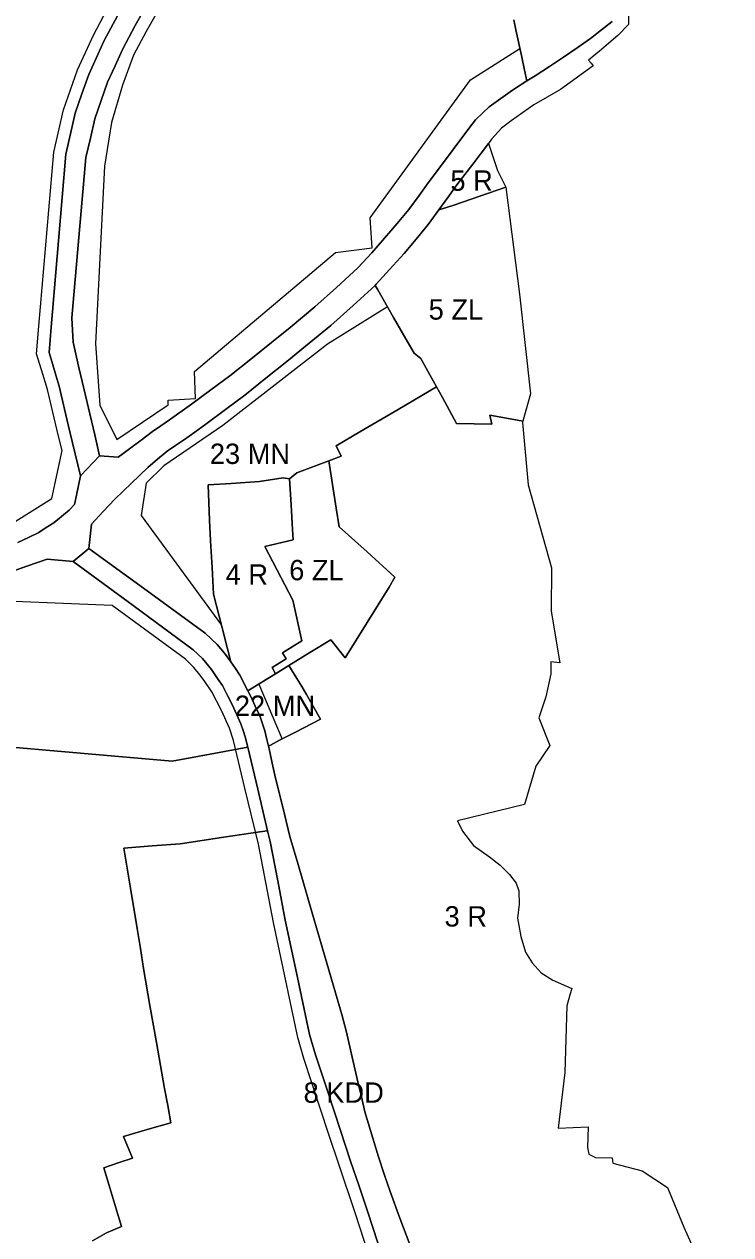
# Model space of a CAD drawing. Extents: x 7423432 to 7425824, y 5537848 to 5539677.
# Drawn here: x 7425463 to 7425809, y 5538619 to 5539213 of the extents above; entities that cross this region are included whole.
import ezdxf

# ---------------------------------------------------------------- set-up
doc = ezdxf.new("R2010")
doc.units = 0
for name, color, linetype in [('linie_rozgraniczajace', 7, 'Continuous'), ('linie_zabudowy_nieprzekraczalne', 7, 'Continuous'), ('oznaczenia_przeznaczen', 7, 'Continuous')]:
    doc.layers.add(name, color=color, linetype=linetype)

msp = doc.modelspace()

# ---------------------------------------------------------------- linework, layer by layer
at = {"layer": 'linie_rozgraniczajace'}
for points in [[(7425545.39, 5539261.91), (7425517.07, 5539212.13), (7425513.94, 5539206.24), (7425510.81, 5539200.35), (7425507.14, 5539192.39), (7425503.47, 5539184.42), (7425500.33, 5539175.37), (7425497.18, 5539166.31), (7425495.01, 5539156.88), (7425493.92, 5539152.15), (7425492.84, 5539147.46), (7425489.35, 5539108.04), (7425485.87, 5539068.62), (7425486.24, 5539062.67), (7425486.61, 5539056.73), (7425487.92, 5539050.83), (7425489.24, 5539044.93), (7425492, 5539033.28), (7425494.75, 5539021.64), (7425497.13, 5539011.32), (7425499.5, 5539001), (7425490.1, 5538991.17), (7425487.54, 5539001.94), (7425484.98, 5539012.7), (7425482.34, 5539023.92), (7425479.7, 5539035.14), (7425478.54, 5539038.97), (7425477.37, 5539042.81), (7425476.04, 5539047.21), (7425474.7, 5539051.61), (7425475.69, 5539064.03), (7425479.31, 5539106.52), (7425482.94, 5539149.01), (7425485.25, 5539159.05), (7425487.56, 5539169.08), (7425490.87, 5539178.62), (7425494.19, 5539188.16), (7425498.02, 5539196.48), (7425501.85, 5539204.79), (7425505.08, 5539210.87), (7425508.3, 5539216.95)], [(7425702.86, 5539214.97), (7425703.93, 5539210), (7425706.63, 5539197.47), (7425708.18, 5539190.31), (7425709.34, 5539184.94), (7425702.19, 5539180.43), (7425696.49, 5539176.35), (7425690.78, 5539172.28), (7425687.48, 5539169.1), (7425684.17, 5539165.91), (7425680.87, 5539161.55), (7425673.12, 5539151.3), (7425665.36, 5539141.04), (7425660.88, 5539134.89), (7425656.4, 5539128.73), (7425651.39, 5539121.79), (7425645.68, 5539114.94), (7425633.18, 5539100.62), (7425626.4, 5539093.16), (7425615.79, 5539083.6), (7425605.18, 5539074.05), (7425593.04, 5539063.98), (7425583.99, 5539056.6), (7425573.73, 5539048.44), (7425563.46, 5539040.29), (7425554.08, 5539033.28), (7425544.69, 5539026.26), (7425533.85, 5539018.56), (7425529.66, 5539015.71), (7425525.47, 5539012.86), (7425519.88, 5539008.65), (7425514.29, 5539004.44), (7425508.62, 5539000.23), (7425499.5, 5539001), (7425497.13, 5539011.32), (7425494.75, 5539021.64), (7425492, 5539033.28), (7425489.24, 5539044.93), (7425487.92, 5539050.83), (7425486.61, 5539056.73), (7425486.24, 5539062.67), (7425485.87, 5539068.62), (7425489.35, 5539108.04), (7425492.84, 5539147.46), (7425493.92, 5539152.15), (7425495.01, 5539156.88), (7425497.18, 5539166.31), (7425500.33, 5539175.37), (7425503.47, 5539184.42), (7425507.14, 5539192.39), (7425510.81, 5539200.35), (7425513.94, 5539206.24), (7425517.07, 5539212.13), (7425545.39, 5539261.91)], [(7425759.44, 5539221.71), (7425759.27, 5539212.59), (7425753.96, 5539207.31), (7425745.02, 5539199.62), (7425739.6, 5539195.09), (7425740.8, 5539193.62), (7425741.84, 5539192.35), (7425725.77, 5539180.84), (7425712.74, 5539173.21), (7425701.62, 5539165.3), (7425696.83, 5539161.76), (7425691.98, 5539156.34), (7425690.44, 5539154.31), (7425682.72, 5539144.1), (7425675, 5539133.89), (7425670.56, 5539127.79), (7425666.12, 5539121.68), (7425660.88, 5539114.43), (7425654.95, 5539107.31), (7425649.02, 5539100.2), (7425641.94, 5539092.42), (7425635.34, 5539085.16), (7425634.8, 5539084.57), (7425623.95, 5539074.81), (7425613.03, 5539064.97), (7425606.85, 5539059.85), (7425600.67, 5539054.72), (7425596.09, 5539050.98), (7425591.52, 5539047.25), (7425581.15, 5539039.02), (7425570.79, 5539030.79), (7425561.27, 5539023.68), (7425551.75, 5539016.57), (7425546.23, 5539012.64), (7425540.7, 5539008.71), (7425536.72, 5539006), (7425532.73, 5539003.29), (7425527.98, 5538999.28), (7425523.23, 5538995.28), (7425515.15, 5538987.49), (7425507.07, 5538979.71), (7425501.3, 5538973.56), (7425495.52, 5538967.42), (7425494.3, 5538955.41), (7425486.63, 5538949.07), (7425473.83, 5538950.21), (7425463.88, 5538946.77), (7425453.09, 5538943)], [(7425508.3, 5539216.95), (7425505.08, 5539210.87), (7425501.85, 5539204.79), (7425498.02, 5539196.48), (7425494.19, 5539188.16), (7425490.87, 5539178.62), (7425487.56, 5539169.08), (7425485.25, 5539159.05), (7425482.94, 5539149.01), (7425479.31, 5539106.52), (7425475.69, 5539064.03), (7425474.7, 5539051.61), (7425476.04, 5539047.21), (7425477.37, 5539042.81)], [(7425459.47, 5538958.37), (7425464.55, 5538960.86), (7425469.69, 5538963.38), (7425473.38, 5538965.72), (7425477.13, 5538968.1), (7425480.88, 5538971.23), (7425484.63, 5538974.36), (7425487.22, 5538977.13), (7425487.53, 5538978.51), (7425488.96, 5538985.54), (7425490.1, 5538991.17), (7425499.5, 5539001), (7425508.62, 5539000.23), (7425514.29, 5539004.44), (7425519.88, 5539008.65), (7425525.47, 5539012.86), (7425529.66, 5539015.71), (7425533.85, 5539018.56), (7425544.69, 5539026.26), (7425554.08, 5539033.28), (7425563.46, 5539040.29), (7425573.73, 5539048.44), (7425583.99, 5539056.6), (7425593.04, 5539063.98), (7425605.18, 5539074.05), (7425615.79, 5539083.6), (7425626.4, 5539093.16), (7425633.18, 5539100.62), (7425645.68, 5539114.94), (7425651.39, 5539121.79), (7425656.4, 5539128.73), (7425660.88, 5539134.89), (7425665.36, 5539141.04), (7425673.12, 5539151.3), (7425680.87, 5539161.55), (7425684.17, 5539165.91), (7425687.48, 5539169.1), (7425690.78, 5539172.28), (7425696.49, 5539176.35), (7425702.19, 5539180.43), (7425709.34, 5539184.94), (7425713.44, 5539187.52), (7425720.39, 5539192.05), (7425727.34, 5539196.58), (7425733.94, 5539201.18), (7425740.54, 5539205.78), (7425745.88, 5539209.99)], [(7425751.22, 5539214.2), (7425745.88, 5539209.99), (7425740.54, 5539205.78), (7425733.94, 5539201.18), (7425727.34, 5539196.58), (7425720.39, 5539192.05), (7425713.44, 5539187.52), (7425709.34, 5539184.94), (7425708.18, 5539190.31), (7425706.63, 5539197.47), (7425703.93, 5539210), (7425702.86, 5539214.97)], [(7425745.88, 5539209.99), (7425751.22, 5539214.2)], [(7425477.37, 5539042.81), (7425478.54, 5539038.97), (7425479.7, 5539035.14), (7425482.34, 5539023.92), (7425484.98, 5539012.7), (7425487.54, 5539001.94), (7425490.1, 5538991.17), (7425488.96, 5538985.54), (7425487.53, 5538978.51), (7425487.22, 5538977.13), (7425484.63, 5538974.36), (7425480.88, 5538971.23), (7425477.13, 5538968.1), (7425473.38, 5538965.72), (7425469.69, 5538963.38), (7425464.55, 5538960.86), (7425459.47, 5538958.37)], [(7425582.48, 5538858.51), (7425583.46, 5538858.97), (7425588.26, 5538861.48), (7425595.71, 5538865.37), (7425607.95, 5538871.76), (7425604.55, 5538877.75), (7425601.15, 5538883.74), (7425598.77, 5538887.7), (7425596.39, 5538891.66), (7425592.46, 5538897.99), (7425602.8, 5538904.34), (7425613.14, 5538910.69), (7425620.07, 5538901.78), (7425630.85, 5538919.1), (7425641.63, 5538936.41), (7425644.52, 5538941.45), (7425630.86, 5538953.77), (7425617.21, 5538966.1), (7425615.62, 5538975.31), (7425613.83, 5538986.92), (7425612.05, 5538998.54), (7425618.09, 5539000.79), (7425615.74, 5539005.9), (7425627.32, 5539012.71), (7425646.14, 5539023.77), (7425664.95, 5539034.84), (7425667.81, 5539029.61), (7425671.3, 5539023.24), (7425674.79, 5539016.88), (7425683.47, 5539016.66), (7425692.16, 5539016.44), (7425691.15, 5539020.85), (7425699.27, 5539019.44), (7425707.4, 5539018.03), (7425707.21, 5539017.36), (7425709.87, 5538986.76), (7425721.38, 5538946.03), (7425721.22, 5538924.65), (7425725.56, 5538899.39), (7425721.1, 5538899.78), (7425721.05, 5538893.94), (7425718.63, 5538882.67), (7425715.25, 5538872.42), (7425720.56, 5538858.73), (7425713.76, 5538848.69), (7425708.22, 5538829.74), (7425675.26, 5538821.86), (7425677.69, 5538816.74), (7425683.06, 5538809.65), (7425690.89, 5538804.11), (7425696.24, 5538800.06), (7425700.72, 5538795.51), (7425704.09, 5538791.26), (7425705.44, 5538787.5), (7425705.47, 5538780.92), (7425704.65, 5538773.98), (7425706.35, 5538764.97), (7425708.56, 5538757.37), (7425711.97, 5538752.1), (7425716.31, 5538747.22), (7425722.1, 5538743.61), (7425731.43, 5538739.49), (7425730.64, 5538736.86), (7425729, 5538731.02), (7425727.93, 5538698.3), (7425724.74, 5538670.95), (7425739.42, 5538671.64), (7425739.03, 5538661.42), (7425739.76, 5538658.25), (7425742.94, 5538656.47), (7425751.15, 5538656.41), (7425751.56, 5538653.72), (7425765.93, 5538650), (7425778.39, 5538641.84), (7425786.3, 5538622.32), (7425809.43, 5538570.89)], [(7425486.63, 5538949.07), (7425494.3, 5538955.41), (7425522.86, 5538934.63), (7425551.42, 5538913.85), (7425557.29, 5538908.3), (7425560.81, 5538904.17), (7425564, 5538899.91), (7425566.22, 5538896.59), (7425568.44, 5538893.26), (7425572.37, 5538885.65), (7425573.82, 5538882.85), (7425575.99, 5538878.05), (7425578.17, 5538873.26), (7425580.63, 5538865.9), (7425581.68, 5538861.69), (7425582.48, 5538858.51), (7425582.81, 5538857.14), (7425584.3, 5538850.08), (7425585.86, 5538842.66), (7425589.43, 5538828.42), (7425593, 5538814.18), (7425597.01, 5538800.34), (7425603.75, 5538777.16), (7425611.14, 5538751.98), (7425618.53, 5538726.79), (7425620.79, 5538718), (7425623.58, 5538705.81), (7425626.36, 5538693.61), (7425628.04, 5538686.29), (7425629.71, 5538678.97), (7425636.41, 5538656.87), (7425639.27, 5538648.33), (7425642.14, 5538639.78), (7425647.02, 5538626.8), (7425651.9, 5538613.83)], [(7425453.09, 5538943), (7425463.88, 5538946.77), (7425473.83, 5538950.21), (7425486.63, 5538949.07), (7425516.08, 5538927.42), (7425545.53, 5538905.76), (7425547.78, 5538903.58), (7425550.03, 5538901.4), (7425553, 5538897.92), (7425554.41, 5538896.03), (7425555.83, 5538894.14), (7425557.82, 5538891.16), (7425559.81, 5538888.17), (7425562.28, 5538883.39), (7425564.75, 5538878.61), (7425568.82, 5538869.46), (7425569.94, 5538866.21), (7425571.05, 5538862.95), (7425572.26, 5538857.89), (7425553.75, 5538854.48), (7425535.23, 5538851.07), (7425490.1, 5538855.01), (7425444.97, 5538858.95)], [(7425545.53, 5538905.76), (7425516.08, 5538927.42), (7425486.63, 5538949.07)], [(7425637.26, 5538611.05), (7425634, 5538621.14), (7425630.74, 5538631.22), (7425626.75, 5538642.98), (7425622.77, 5538654.73), (7425617.82, 5538669.72), (7425611.69, 5538688.29), (7425605.55, 5538706.86), (7425602.6, 5538716.88), (7425596.66, 5538744.94), (7425590.72, 5538773.01), (7425587.03, 5538792.29), (7425583.34, 5538811.57), (7425582.05, 5538816.96), (7425577.19, 5538837.26), (7425572.26, 5538857.89), (7425571.05, 5538862.95), (7425569.94, 5538866.21), (7425568.82, 5538869.46), (7425564.75, 5538878.61), (7425562.28, 5538883.39), (7425559.81, 5538888.17), (7425557.82, 5538891.16), (7425555.83, 5538894.14), (7425554.41, 5538896.03), (7425553, 5538897.92), (7425550.03, 5538901.4), (7425547.78, 5538903.58), (7425545.53, 5538905.76)], [(7425444.97, 5538858.95), (7425490.1, 5538855.01), (7425535.23, 5538851.07), (7425553.75, 5538854.48), (7425572.26, 5538857.89), (7425577.19, 5538837.26), (7425582.05, 5538816.96), (7425578.13, 5538816.36), (7425560.56, 5538813.71), (7425539.07, 5538810.47), (7425525.27, 5538809.46), (7425511.47, 5538808.44), (7425514.74, 5538788.7), (7425518.01, 5538768.96), (7425519.56, 5538759.14), (7425521.11, 5538749.33), (7425524.27, 5538731.16), (7425527.42, 5538712.98), (7425529.45, 5538701.67), (7425531.47, 5538690.36), (7425532.97, 5538681.99), (7425534.47, 5538673.61), (7425522.84, 5538670.26), (7425511.22, 5538666.91), (7425515.63, 5538656.25), (7425508.58, 5538653.86), (7425501.54, 5538651.47), (7425504.77, 5538641.11), (7425507.55, 5538631.9), (7425510.34, 5538622.69), (7425506.05, 5538620.89), (7425502.97, 5538619.64), (7425496.08, 5538615.71)], [(7425647.02, 5538626.8), (7425642.14, 5538639.78), (7425639.27, 5538648.33), (7425636.41, 5538656.87), (7425629.71, 5538678.97), (7425628.04, 5538686.29), (7425626.36, 5538693.61), (7425623.58, 5538705.81), (7425620.79, 5538718), (7425618.53, 5538726.79), (7425611.14, 5538751.98), (7425603.75, 5538777.16), (7425597.01, 5538800.34), (7425593, 5538814.18), (7425589.43, 5538828.42), (7425585.86, 5538842.66), (7425584.3, 5538850.08), (7425582.81, 5538857.14), (7425582.48, 5538858.51)], [(7425496.08, 5538615.71), (7425502.97, 5538619.64), (7425506.05, 5538620.89), (7425510.34, 5538622.69), (7425507.55, 5538631.9), (7425504.77, 5538641.11), (7425501.54, 5538651.47), (7425508.58, 5538653.86), (7425515.63, 5538656.25), (7425511.22, 5538666.91), (7425522.84, 5538670.26), (7425534.47, 5538673.61), (7425532.97, 5538681.99), (7425531.47, 5538690.36), (7425529.45, 5538701.67), (7425527.42, 5538712.98), (7425524.27, 5538731.16), (7425521.11, 5538749.33), (7425519.56, 5538759.14), (7425518.01, 5538768.96), (7425514.74, 5538788.7), (7425511.47, 5538808.44), (7425525.27, 5538809.46), (7425539.07, 5538810.47), (7425560.56, 5538813.71), (7425578.13, 5538816.36), (7425582.05, 5538816.96), (7425583.34, 5538811.57), (7425587.03, 5538792.29), (7425590.72, 5538773.01), (7425596.66, 5538744.94), (7425602.6, 5538716.88), (7425605.55, 5538706.86), (7425611.69, 5538688.29), (7425617.82, 5538669.72), (7425622.77, 5538654.73), (7425626.75, 5538642.98), (7425630.74, 5538631.22), (7425634, 5538621.14), (7425637.26, 5538611.05)], [(7425651.9, 5538613.83), (7425647.02, 5538626.8)]]:
    msp.add_lwpolyline(points, dxfattribs=at)
for points in [[(7425666.12, 5539121.68), (7425670.56, 5539127.79), (7425675, 5539133.89), (7425682.72, 5539144.1), (7425690.44, 5539154.31), (7425694.94, 5539141.04), (7425699.02, 5539132.75), (7425681.98, 5539126.98), (7425673.49, 5539123.95), (7425669.8, 5539122.81)], [(7425634.8, 5539084.57), (7425635.34, 5539085.16), (7425641.94, 5539092.42), (7425649.02, 5539100.2), (7425654.95, 5539107.31), (7425660.88, 5539114.43), (7425666.12, 5539121.68), (7425669.8, 5539122.81), (7425673.49, 5539123.95), (7425681.98, 5539126.98), (7425699.02, 5539132.75), (7425705.65, 5539080.27), (7425711.13, 5539031.37), (7425707.4, 5539018.03), (7425699.27, 5539019.44), (7425691.15, 5539020.85), (7425692.16, 5539016.44), (7425683.47, 5539016.66), (7425674.79, 5539016.88), (7425671.3, 5539023.24), (7425667.81, 5539029.61), (7425664.95, 5539034.84), (7425662.56, 5539039.2), (7425657.31, 5539048.79), (7425653.9, 5539051.4), (7425651.63, 5539055.33), (7425643.85, 5539068.84), (7425636.08, 5539082.35)], [(7425494.3, 5538955.41), (7425495.52, 5538967.42), (7425501.3, 5538973.56), (7425507.07, 5538979.71), (7425515.15, 5538987.49), (7425523.23, 5538995.28), (7425527.98, 5538999.28), (7425532.73, 5539003.29), (7425536.72, 5539006), (7425540.7, 5539008.71), (7425546.23, 5539012.64), (7425551.75, 5539016.57), (7425561.27, 5539023.68), (7425570.79, 5539030.79), (7425581.15, 5539039.02), (7425591.52, 5539047.25), (7425596.09, 5539050.98), (7425600.67, 5539054.72), (7425606.85, 5539059.85), (7425613.03, 5539064.97), (7425623.95, 5539074.81), (7425634.8, 5539084.57), (7425636.08, 5539082.35), (7425643.85, 5539068.84), (7425651.63, 5539055.33), (7425653.9, 5539051.4), (7425657.31, 5539048.79), (7425662.56, 5539039.2), (7425664.95, 5539034.84), (7425646.14, 5539023.77), (7425627.32, 5539012.71), (7425615.74, 5539005.9), (7425618.09, 5539000.79), (7425612.05, 5538998.54), (7425596.38, 5538992.68), (7425592.72, 5538989.69), (7425589.71, 5538990.19), (7425577.97, 5538988.33), (7425564.09, 5538987.42), (7425552.89, 5538986.69), (7425553.44, 5538969.4), (7425554.02, 5538959.17), (7425554.77, 5538946.08), (7425555.52, 5538932.99), (7425559.76, 5538916.45), (7425562.38, 5538906.2), (7425564, 5538899.91), (7425560.81, 5538904.17), (7425557.29, 5538908.3), (7425551.42, 5538913.85), (7425522.86, 5538934.63)], [(7425580.72, 5538956.41), (7425594.57, 5538959.7), (7425594.14, 5538967.56), (7425593.94, 5538971.05), (7425593.38, 5538979.53), (7425592.72, 5538989.69), (7425596.38, 5538992.68), (7425612.05, 5538998.54), (7425613.83, 5538986.92), (7425615.62, 5538975.31), (7425617.21, 5538966.1), (7425630.86, 5538953.77), (7425644.52, 5538941.45), (7425641.63, 5538936.41), (7425630.85, 5538919.1), (7425620.07, 5538901.78), (7425613.14, 5538910.69), (7425602.8, 5538904.34), (7425592.46, 5538897.99), (7425585.87, 5538893.95), (7425584.25, 5538897.05), (7425587.68, 5538899.16), (7425591.12, 5538901.27), (7425589.29, 5538904.25), (7425598.84, 5538910.12), (7425594.38, 5538930.13)], [(7425553.44, 5538969.4), (7425552.89, 5538986.69), (7425564.09, 5538987.42), (7425577.97, 5538988.33), (7425589.71, 5538990.19), (7425592.72, 5538989.69), (7425593.38, 5538979.53), (7425593.94, 5538971.05), (7425594.14, 5538967.56), (7425594.57, 5538959.7), (7425580.72, 5538956.41), (7425594.38, 5538930.13), (7425598.84, 5538910.12), (7425589.29, 5538904.25), (7425591.12, 5538901.27), (7425587.68, 5538899.16), (7425584.25, 5538897.05), (7425585.87, 5538893.95), (7425579.12, 5538889.8), (7425572.37, 5538885.65), (7425568.44, 5538893.26), (7425566.22, 5538896.59), (7425564, 5538899.91), (7425562.38, 5538906.2), (7425559.76, 5538916.45), (7425555.52, 5538932.99), (7425554.77, 5538946.08), (7425554.02, 5538959.17)], [(7425572.37, 5538885.65), (7425579.12, 5538889.8), (7425585.87, 5538893.95), (7425592.46, 5538897.99), (7425596.39, 5538891.66), (7425598.77, 5538887.7), (7425601.15, 5538883.74), (7425604.55, 5538877.75), (7425607.95, 5538871.76), (7425595.71, 5538865.37), (7425588.26, 5538861.48), (7425583.46, 5538858.97), (7425582.48, 5538858.51), (7425581.68, 5538861.69), (7425580.63, 5538865.9), (7425578.17, 5538873.26), (7425575.99, 5538878.05), (7425573.82, 5538882.85)]]:
    msp.add_lwpolyline(points, close=True, dxfattribs=at)
at = {"layer": 'linie_zabudowy_nieprzekraczalne'}
for points in [[(7425558.24, 5539272.38), (7425522.32, 5539209.24), (7425516.19, 5539197.69), (7425510.83, 5539182.93), (7425505.36, 5539164.51), (7425501.98, 5539143.17), (7425497.59, 5539056.11), (7425499.66, 5539025.85), (7425499.66, 5539025.85), (7425499.66, 5539025.85), (7425508.05, 5539009.01), (7425533.22, 5539026.02), (7425533.13, 5539028.28), (7425546.7, 5539029.09), (7425546.16, 5539042.4), (7425615.32, 5539100.82), (7425633.36, 5539103.07), (7425632.41, 5539117.79), (7425681.7, 5539185.49), (7425705.88, 5539200.96)], [(7425452.92, 5538965.48), (7425476.15, 5538979.97), (7425481.09, 5539003.51), (7425479.14, 5539011.32), (7425473.9, 5539033.58), (7425471.63, 5539041.06), (7425468.63, 5539050.95), (7425469.71, 5539064.52), (7425477, 5539149.95), (7425481.78, 5539170.74), (7425488.62, 5539190.41), (7425496.47, 5539207.46), (7425503.05, 5539219.84)], [(7425640.84, 5539074.08), (7425611.4, 5539055.75), (7425560.12, 5539015.9), (7425531.01, 5538996.01), (7425522.35, 5538987.58), (7425519.97, 5538971.7), (7425559.4, 5538917.85)], [(7425570.88, 5538837.86), (7425565.28, 5538861.28), (7425563.23, 5538867.27), (7425559.34, 5538876.01), (7425554.63, 5538885.12), (7425550.93, 5538890.67), (7425548.31, 5538894.17), (7425545.65, 5538897.29), (7425541.65, 5538901.17), (7425505.77, 5538927.55), (7425433.63, 5538930.47)], [(7425577.68, 5538888.91), (7425589.15, 5538861.94)], [(7425403.1, 5538467.28), (7425472.86, 5538474.66), (7425481.7, 5538475.74), (7425635.24, 5538496.85), (7425636.24, 5538494.22), (7425636.24, 5538494.22), (7425672.06, 5538507.66), (7425659.74, 5538532.64), (7425653.28, 5538544.99), (7425648.13, 5538557.43), (7425639.35, 5538584.86), (7425631.55, 5538609.21), (7425625.04, 5538629.34), (7425617.08, 5538652.83), (7425612.13, 5538667.84), (7425599.82, 5538705.08), (7425596.78, 5538715.41), (7425584.84, 5538771.82), (7425577.47, 5538810.31), (7425570.88, 5538837.86)]]:
    msp.add_lwpolyline(points, dxfattribs=at)

# ---------------------------------------------------------------- texts
at = {"layer": 'oznaczenia_przeznaczen'}
for s, p in [('5 R', (7425671.76, 5539131.05)), ('5 ZL', (7425661.09, 5539067.8)), ('23 MN', (7425553.65, 5538996.96)), ('6 ZL', (7425592.62, 5538939.87)), ('4 R', (7425561.4, 5538937.67)), ('22 MN', (7425565.95, 5538873.28)), ('3 R', (7425668.9, 5538769.9)), ('8 KDD', (7425599.68, 5538683.4))]:
    msp.add_text(s, height=10, dxfattribs=at).set_placement(p)

doc.saveas('drawing.dxf')
